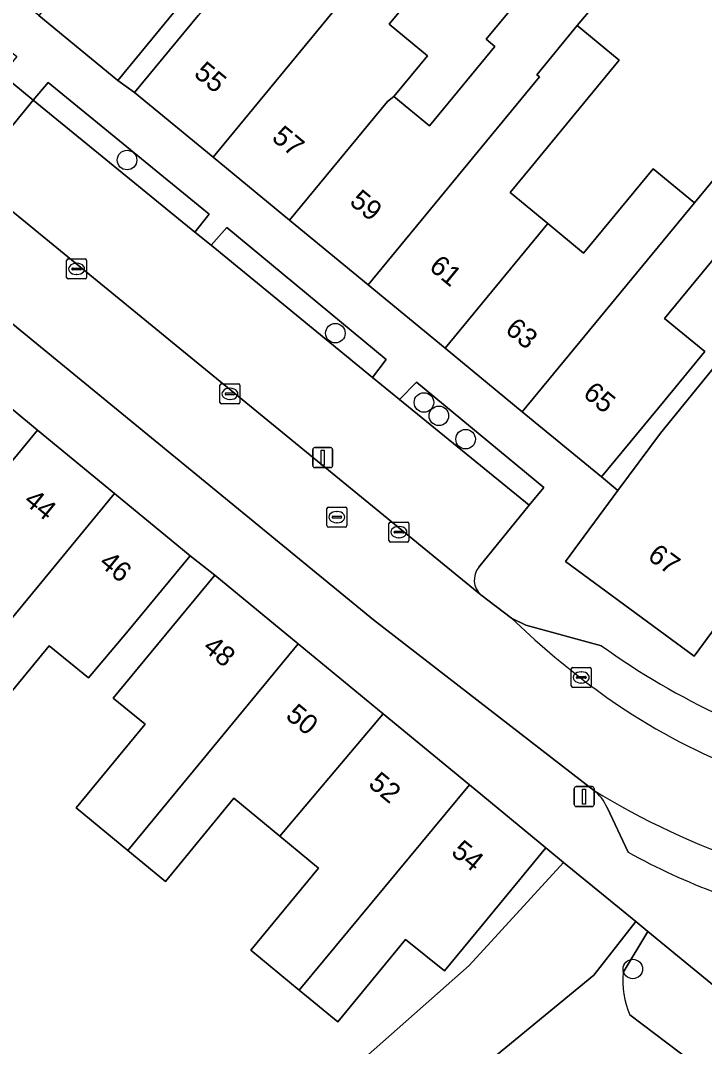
# Model space of a CAD drawing. Extents: x 160157 to 160921, y 381516 to 382045.
# Drawn here: x 160451.2 to 160485.5, y 381805.6 to 381857 of the extents above; entities that cross this region are included whole.
import ezdxf

# ---------------------------------------------------------------- set-up
doc = ezdxf.new("R2010")
doc.units = 0
for name, color, linetype in [('IMGEO_Boom', 7, 'Continuous'), ('IMGEO_Erf', 7, 'Continuous'), ('IMGEO_Groenvoorziening', 7, 'Continuous'), ('IMGEO_Haag', 7, 'Continuous'), ('IMGEO_Kolk', 7, 'Continuous'), ('IMGEO_Lichtmast', 7, 'Continuous'), ('IMGEO_Pand', 7, 'Continuous'), ('IMGEO_Pand_nummerreeks', 7, 'Continuous'), ('IMGEO_Parkeervlak_open', 7, 'Continuous'), ('IMGEO_Rijbaan_lokaal_open', 7, 'Continuous'), ('IMGEO_Rioolput', 7, 'Continuous'), ('IMGEO_Voetpad_open', 7, 'Continuous')]:
    doc.layers.add(name, color=color, linetype=linetype)

msp = doc.modelspace()

# ---------------------------------------------------------------- linework, layer by layer
at = {"layer": 'IMGEO_Boom'}
for centre in [(160456.558, 381849.982), (160466.984, 381841.312), (160471.416, 381837.846), (160472.165, 381837.178), (160473.501, 381836.005), (160481.873, 381809.475)]:
    msp.add_circle(centre, 0.489, dxfattribs=at)
at = {"layer": 'IMGEO_Erf'}
for points in [[(160471.394, 381858.876), (160469.674, 381856.788), (160471.592, 381855.209), (160469.913, 381853.17), (160471.694, 381851.703), (160474.964, 381855.673), (160474.528, 381856.033), (160477.246, 381859.334)], [(160459.274, 381857.827), (160456.095, 381853.967), (160456.94, 381853.363), (160460.119, 381857.223)], [(160479.63, 381857.37), (160479.092, 381856.716), (160481.189, 381854.989), (160479.162, 381852.527), (160476.764, 381849.616), (160475.727, 381848.357), (160477.617, 381846.8), (160479.405, 381845.327), (160482.885, 381849.552), (160484.957, 381847.845), (160488.178, 381851.756)], [(160486.907, 381846.238), (160483.459, 381842.052), (160485.473, 381840.393), (160483.484, 381837.978), (160480.304, 381834.119), (160481.128, 381833.441), (160483.249, 381836.314), (160489.523, 381844.017)], [(160463.455, 381800.599), (160473.68, 381809.649), (160478.409, 381814.815), (160477.522, 381815.543), (160474.343, 381811.684), (160472.453, 381809.383), (160470.492, 381810.944), (160467.104, 381806.83), (160465.181, 381808.414), (160462.754, 381810.413), (160466.144, 381814.529), (160464.2, 381816.13), (160461.903, 381818.022), (160458.478, 381813.864), (160456.602, 381815.409), (160454.011, 381817.543), (160457.458, 381821.727), (160455.872, 381823.033), (160457.769, 381825.336), (160460.948, 381829.195), (160459.714, 381830.173), (160456.536, 381826.314), (160454.63, 381824.057), (160452.667, 381825.655), (160449.283, 381821.546)]]:
    msp.add_lwpolyline(points, dxfattribs=at)
at = {"layer": 'IMGEO_Groenvoorziening'}
for points in [[(160452.613, 381853.874), (160451.861, 381852.989), (160459.954, 381846.377), (160460.677, 381847.27)], [(160461.55, 381846.608), (160460.774, 381845.714), (160468.837, 381839.099), (160469.523, 381839.994)], [(160471.046, 381838.864), (160470.196, 381837.991), (160476.678, 381832.706), (160477.421, 381833.581)], [(160458.371, 381791.432), (160479.918, 381809.167), (160482.021, 381811.85), (160478.409, 381814.815), (160473.68, 381809.649), (160463.455, 381800.599), (160460.339, 381798.072), (160458.209, 381794.524)]]:
    msp.add_lwpolyline(points, close=True, dxfattribs=at)
for points in [[(160481.387, 381809.302), (160482.629, 381811.351), (160482.021, 381811.85), (160479.918, 381809.167), (160458.371, 381791.432), (160458.948, 381780.395), (160474.146, 381779.946), (160474.316, 381782.426), (160495.817, 381780.983), (160495.853, 381781.955), (160492.048, 381782.329), (160492.577, 381797.21), (160490.36, 381800.636), (160481.716, 381807.178)], [(160481.716, 381807.178), (160490.36, 381800.636), (160492.577, 381797.21), (160492.048, 381782.329), (160495.853, 381781.955), (160496.537, 381799.933), (160482.629, 381811.351), (160481.387, 381809.302)]]:
    msp.add_lwpolyline(points, dxfattribs=at)
msp.add_arc((160485.875, 381808.91), 4.505, 175.0051, 202.6048, dxfattribs=at)
msp.add_arc((160485.875, 381808.91), 4.505, 175.0051, 202.6048, dxfattribs=at)
at = {"layer": 'IMGEO_Haag'}
for points in [[(160451.861, 381852.989), (160459.954, 381846.377), (160460.677, 381847.27), (160452.613, 381853.874)], [(160460.774, 381845.714), (160468.837, 381839.099), (160469.523, 381839.994), (160461.55, 381846.608)], [(160476.678, 381832.706), (160477.421, 381833.581), (160471.046, 381838.864), (160470.196, 381837.991)]]:
    msp.add_lwpolyline(points, close=True, dxfattribs=at)
at = {"layer": 'IMGEO_Kolk'}
for p, q in [((160453.535, 381844.107), (160453.535, 381844.959)), ((160453.61, 381845.033), (160454.462, 381845.033)), ((160453.794, 381844.527), (160453.794, 381844.539)), ((160453.837, 381844.576), (160454.235, 381844.576)), ((160454.023, 381844.813), (160454.048, 381844.813)), ((160454.278, 381844.539), (160454.278, 381844.527)), ((160454.536, 381844.959), (160454.536, 381844.107)), ((160454.462, 381844.033), (160453.61, 381844.033)), ((160454.232, 381844.49), (160453.834, 381844.49)), ((160454.046, 381844.253), (160454.021, 381844.253)), ((160461.209, 381837.851), (160461.209, 381838.703)), ((160461.284, 381838.777), (160462.136, 381838.777)), ((160461.697, 381838.557), (160461.722, 381838.557)), ((160462.21, 381838.703), (160462.21, 381837.851)), ((160461.468, 381838.271), (160461.468, 381838.283)), ((160461.906, 381838.234), (160461.508, 381838.234)), ((160461.511, 381838.32), (160461.909, 381838.32)), ((160461.72, 381837.997), (160461.695, 381837.997)), ((160461.952, 381838.283), (160461.952, 381838.271)), ((160462.136, 381837.777), (160461.284, 381837.777)), ((160469.666, 381830.928), (160469.666, 381831.78)), ((160469.741, 381831.854), (160470.593, 381831.854)), ((160470.667, 381831.78), (160470.667, 381830.928)), ((160469.925, 381831.348), (160469.925, 381831.36)), ((160470.363, 381831.311), (160469.965, 381831.311)), ((160469.968, 381831.397), (160470.366, 381831.397)), ((160470.154, 381831.634), (160470.179, 381831.634)), ((160470.409, 381831.36), (160470.409, 381831.348)), ((160470.593, 381830.854), (160469.741, 381830.854)), ((160470.177, 381831.074), (160470.152, 381831.074)), ((160478.791, 381823.65), (160478.791, 381824.502)), ((160478.866, 381824.576), (160479.718, 381824.576)), ((160479.792, 381824.502), (160479.792, 381823.65)), ((160479.05, 381824.07), (160479.05, 381824.082)), ((160479.488, 381824.033), (160479.09, 381824.033)), ((160479.093, 381824.119), (160479.491, 381824.119)), ((160479.279, 381824.356), (160479.304, 381824.356)), ((160479.534, 381824.082), (160479.534, 381824.07)), ((160479.718, 381823.576), (160478.866, 381823.576)), ((160479.302, 381823.796), (160479.277, 381823.796))]:
    msp.add_line(p, q, dxfattribs=at)
for points in [[(160453.535, 381844.107), (160453.535, 381844.959)], [(160453.61, 381845.033), (160454.462, 381845.033)], [(160454.536, 381844.959), (160454.536, 381844.107)], [(160454.462, 381844.033), (160453.61, 381844.033)], [(160461.209, 381837.851), (160461.209, 381838.703)], [(160461.284, 381838.777), (160462.136, 381838.777)], [(160462.21, 381838.703), (160462.21, 381837.851)], [(160462.136, 381837.777), (160461.284, 381837.777)], [(160469.666, 381830.928), (160469.666, 381831.78)], [(160469.741, 381831.854), (160470.593, 381831.854)], [(160470.667, 381831.78), (160470.667, 381830.928)], [(160470.593, 381830.854), (160469.741, 381830.854)], [(160478.791, 381823.65), (160478.791, 381824.502)], [(160478.866, 381824.576), (160479.718, 381824.576)], [(160479.792, 381824.502), (160479.792, 381823.65)], [(160479.718, 381823.576), (160478.866, 381823.576)]]:
    msp.add_lwpolyline(points, dxfattribs=at)
for centre, radius, start, end in [((160453.612, 381844.957), 0.0765, 91.552, 178.448), ((160453.612, 381844.957), 0.0765, 91.552, 178.448), ((160453.834, 381844.536), 0.0403, 85.8775, 175.7526), ((160454.239, 381844.538), 0.0386, 1.7309, 96.639), ((160454.46, 381844.957), 0.0765, 1.552, 88.448), ((160454.46, 381844.957), 0.0765, 1.552, 88.448), ((160453.612, 381844.109), 0.0765, 181.552, 268.448), ((160453.612, 381844.109), 0.0765, 181.552, 268.448), ((160453.831, 381844.526), 0.0366, 178.938, 274.7102), ((160454.235, 381844.533), 0.043, 264.8664, 352.4533), ((160454.46, 381844.109), 0.0765, 271.552, 358.448), ((160454.46, 381844.109), 0.0765, 271.552, 358.448), ((160461.286, 381838.701), 0.0765, 91.552, 178.448), ((160461.286, 381838.701), 0.0765, 91.552, 178.448), ((160462.134, 381838.701), 0.0765, 1.552, 88.448), ((160462.134, 381838.701), 0.0765, 1.552, 88.448), ((160461.508, 381838.28), 0.0403, 85.8775, 175.7526), ((160461.505, 381838.27), 0.0366, 178.938, 274.7102), ((160461.909, 381838.277), 0.043, 264.8664, 352.4533), ((160461.913, 381838.282), 0.0386, 1.7309, 96.639), ((160461.286, 381837.853), 0.0765, 181.552, 268.448), ((160461.286, 381837.853), 0.0765, 181.552, 268.448), ((160462.134, 381837.853), 0.0765, 271.552, 358.448), ((160462.134, 381837.853), 0.0765, 271.552, 358.448), ((160469.743, 381831.778), 0.0765, 91.552, 178.448), ((160469.743, 381831.778), 0.0765, 91.552, 178.448), ((160470.591, 381831.778), 0.0765, 1.552, 88.448), ((160470.591, 381831.778), 0.0765, 1.552, 88.448), ((160469.965, 381831.357), 0.0403, 85.8775, 175.7526), ((160469.962, 381831.347), 0.0366, 178.938, 274.7102), ((160470.366, 381831.354), 0.043, 264.8664, 352.4533), ((160470.37, 381831.359), 0.0386, 1.7309, 96.639), ((160469.743, 381830.93), 0.0765, 181.552, 268.448), ((160469.743, 381830.93), 0.0765, 181.552, 268.448), ((160470.591, 381830.93), 0.0765, 271.552, 358.448), ((160470.591, 381830.93), 0.0765, 271.552, 358.448), ((160478.868, 381824.5), 0.0765, 91.552, 178.448), ((160478.868, 381824.5), 0.0765, 91.552, 178.448), ((160479.716, 381824.5), 0.0765, 1.552, 88.448), ((160479.716, 381824.5), 0.0765, 1.552, 88.448), ((160479.09, 381824.079), 0.0403, 85.8775, 175.7526), ((160479.087, 381824.069), 0.0366, 178.938, 274.7102), ((160479.491, 381824.076), 0.043, 264.8664, 352.4533), ((160479.495, 381824.081), 0.0386, 1.7309, 96.639), ((160478.868, 381823.652), 0.0765, 181.552, 268.448), ((160478.868, 381823.652), 0.0765, 181.552, 268.448), ((160479.716, 381823.652), 0.0765, 271.552, 358.448), ((160479.716, 381823.652), 0.0765, 271.552, 358.448)]:
    msp.add_arc(centre, radius, start, end, dxfattribs=at)
for centre, major_axis, ratio, start_param, end_param in [((160454.022, 381844.533), (-0.387, 0.002), 0.722429, 4.712389, 7.853982), ((160454.047, 381844.533), (-0.39, 0.002), 0.717154, 1.570796, 4.712389), ((160461.696, 381838.277), (-0.387, 0.002), 0.722429, 4.712389, 7.853982), ((160461.721, 381838.277), (-0.39, 0.002), 0.717154, 1.570796, 4.712389), ((160470.153, 381831.354), (-0.387, 0.002), 0.722429, 4.712389, 7.853982), ((160470.178, 381831.354), (-0.39, 0.002), 0.717154, 1.570796, 4.712389), ((160479.278, 381824.076), (-0.387, 0.002), 0.722429, 4.712389, 7.853982), ((160479.303, 381824.076), (-0.39, 0.002), 0.717154, 1.570796, 4.712389)]:
    msp.add_ellipse(centre, major_axis=major_axis, ratio=ratio, start_param=start_param, end_param=end_param, dxfattribs=at)
at = {"layer": 'IMGEO_Lichtmast'}
for p, q in [((160465.854, 381834.684), (160465.854, 381835.484)), ((160465.854, 381835.484), (160465.854, 381834.684)), ((160465.954, 381835.584), (160466.744, 381835.584)), ((160466.744, 381835.584), (160465.954, 381835.584)), ((160466.844, 381835.484), (160466.844, 381834.684)), ((160466.844, 381834.684), (160466.844, 381835.484)), ((160466.744, 381834.584), (160465.954, 381834.584)), ((160465.954, 381834.584), (160466.744, 381834.584)), ((160478.94, 381817.712), (160478.94, 381818.512)), ((160478.94, 381818.512), (160478.94, 381817.712)), ((160479.04, 381818.612), (160479.83, 381818.612)), ((160479.83, 381818.612), (160479.04, 381818.612)), ((160479.93, 381818.512), (160479.93, 381817.712)), ((160479.93, 381817.712), (160479.93, 381818.512)), ((160479.83, 381817.612), (160479.04, 381817.612)), ((160479.04, 381817.612), (160479.83, 381817.612))]:
    msp.add_line(p, q, dxfattribs=at)
for points in [[(160466.274, 381835.459), (160466.424, 381835.459), (160466.424, 381834.709), (160466.274, 381834.709), (160466.274, 381835.459)], [(160479.36, 381818.487), (160479.51, 381818.487), (160479.51, 381817.737), (160479.36, 381817.737), (160479.36, 381818.487)]]:
    msp.add_lwpolyline(points, dxfattribs=at)
for centre, start, end in [((160465.954, 381835.484), 90, 180), ((160465.954, 381835.484), 90, 180), ((160466.744, 381835.484), 0, 90), ((160466.744, 381835.484), 360, 90), ((160465.954, 381834.684), 180, 270), ((160465.954, 381834.684), 180, 270), ((160466.744, 381834.684), 270, 0), ((160466.744, 381834.684), 270, 0), ((160479.04, 381818.512), 90, 180), ((160479.04, 381818.512), 90, 180), ((160479.83, 381818.512), 0, 90), ((160479.83, 381818.512), 360, 90), ((160479.04, 381817.712), 180, 270), ((160479.04, 381817.712), 180, 270), ((160479.83, 381817.712), 270, 0), ((160479.83, 381817.712), 270, 0)]:
    msp.add_arc(centre, 0.1, start, end, dxfattribs=at)
at = {"layer": 'IMGEO_Pand'}
for points in [[(160460.843, 381867.566), (160452.138, 381857.227), (160456.095, 381853.967), (160459.274, 381857.827), (160461.232, 381860.205), (160459.299, 381861.797), (160462.754, 381865.991)], [(160469.412, 381860.508), (160467.333, 381862.221), (160465.488, 381863.741), (160462.036, 381859.55), (160460.119, 381857.223), (160456.94, 381853.363), (160460.864, 381850.131)], [(160469.412, 381860.508), (160460.864, 381850.131), (160464.696, 381846.974), (160469.59, 381852.916), (160469.913, 381853.17), (160471.592, 381855.209), (160469.674, 381856.788), (160471.394, 381858.876)], [(160479.092, 381856.716), (160479.63, 381857.37), (160477.246, 381859.334), (160474.528, 381856.033), (160474.964, 381855.673), (160471.694, 381851.703), (160469.913, 381853.17), (160469.59, 381852.916), (160464.696, 381846.974), (160468.622, 381843.741), (160477.193, 381854.149), (160477.065, 381854.255)], [(160475.727, 381848.357), (160476.764, 381849.616), (160479.162, 381852.527), (160481.189, 381854.989), (160479.092, 381856.716), (160477.065, 381854.255), (160477.193, 381854.149), (160468.622, 381843.741), (160472.481, 381840.563), (160477.617, 381846.8)], [(160483.459, 381842.052), (160486.907, 381846.238), (160490.129, 381850.149), (160488.178, 381851.756), (160484.957, 381847.845), (160476.341, 381837.384), (160480.304, 381834.119), (160483.484, 381837.978), (160485.473, 381840.393)], [(160477.617, 381846.8), (160472.481, 381840.563), (160476.341, 381837.384), (160484.957, 381847.845), (160482.885, 381849.552), (160479.405, 381845.327)], [(160489.609, 381831.618), (160489.422, 381831.756), (160493.577, 381836.913), (160492.694, 381837.625), (160493.273, 381838.344), (160492.975, 381838.584), (160494.435, 381840.297), (160489.523, 381844.017), (160483.249, 381836.314), (160481.128, 381833.441), (160478.504, 381829.886), (160484.936, 381825.138), (160487.416, 381828.497), (160487.323, 381828.564)], [(160452.077, 381836.463), (160448.406, 381839.488), (160443.287, 381833.299), (160443.023, 381833.517), (160439.599, 381829.365), (160439.859, 381829.155), (160441.282, 381828.006), (160439.398, 381825.673), (160441.698, 381823.816), (160443.582, 381826.149)], [(160447.474, 381823.007), (160450.737, 381826.969), (160455.926, 381833.293), (160452.077, 381836.463), (160443.582, 381826.149)], [(160452.667, 381825.655), (160454.63, 381824.057), (160456.536, 381826.314), (160459.714, 381830.173), (160455.926, 381833.293), (160450.737, 381826.969), (160447.474, 381823.007), (160449.283, 381821.546)], [(160456.602, 381815.409), (160465.126, 381825.753), (160460.948, 381829.195), (160457.769, 381825.336), (160455.872, 381823.033), (160457.458, 381821.727), (160454.011, 381817.543)], [(160469.377, 381822.252), (160465.126, 381825.753), (160456.602, 381815.409), (160458.478, 381813.864), (160461.903, 381818.022), (160464.2, 381816.13)], [(160473.701, 381818.691), (160469.377, 381822.252), (160464.2, 381816.13), (160466.144, 381814.529), (160462.754, 381810.413), (160465.181, 381808.414)], [(160473.701, 381818.691), (160465.181, 381808.414), (160467.104, 381806.83), (160470.492, 381810.944), (160472.453, 381809.383), (160474.343, 381811.684), (160477.522, 381815.543)]]:
    msp.add_lwpolyline(points, close=True, dxfattribs=at)
at = {"layer": 'IMGEO_Parkeervlak_open'}
for points in [[(160460.774, 381845.714), (160459.954, 381846.377), (160451.861, 381852.989), (160448.706, 381849.132), (160474.266, 381828.22)], [(160474.16, 381829.592), (160476.678, 381832.706), (160470.196, 381837.991), (160468.837, 381839.099), (160460.774, 381845.714)], [(160480.308, 381825.664), (160476.51, 381826.689), (160475.803, 381827.039), (160476.974, 381825.958)], [(160480.58, 381817.558), (160481.638, 381815.33)]]:
    msp.add_lwpolyline(points, dxfattribs=at)
for centre, radius, start, end in [((160474.931, 381828.961), 0.996, 140.7314, 228.1043), ((160506.37, 381858.968), 44.202, 228.3147, 235.141), ((160501.525, 381854.933), 36.15, 234.0616, 256.3354), ((160500.209, 381851.371), 34.454, 236.3269, 248.3483), ((160499.758, 381850.577), 37.779, 238.2924, 251.4783), ((160478.583, 381816.719), 2.166, 22.7987, 52.4896), ((160497.263, 381843.305), 32.043, 240.8151, 258.495)]:
    msp.add_arc(centre, radius, start, end, dxfattribs=at)
at = {"layer": 'IMGEO_Rijbaan_lokaal_open'}
for points in [[(160371.41, 381914.519), (160389.742, 381899.391), (160409.362, 381883.2), (160421.079, 381873.531), (160420.73, 381873.107), (160425.014, 381863.084), (160439.434, 381851.118), (160468.894, 381826.952), (160479.902, 381818.437)], [(160476.974, 381825.958), (160475.803, 381827.039), (160474.266, 381828.22), (160448.706, 381849.132), (160447.149, 381850.406), (160434.38, 381860.853), (160429.948, 381864.485)]]:
    msp.add_lwpolyline(points, dxfattribs=at)
for centre, radius, start, end in [((160506.37, 381858.968), 44.202, 228.3147, 235.141), ((160500.209, 381851.371), 34.454, 236.3269, 248.3483), ((160499.758, 381850.577), 37.779, 238.2924, 251.4783)]:
    msp.add_arc(centre, radius, start, end, dxfattribs=at)
at = {"layer": 'IMGEO_Rioolput'}
for p, q in [((160466.56, 381831.676), (160466.56, 381832.528)), ((160466.635, 381832.602), (160467.487, 381832.602)), ((160467.048, 381832.382), (160467.073, 381832.382)), ((160467.561, 381832.528), (160467.561, 381831.676)), ((160466.819, 381832.096), (160466.819, 381832.108)), ((160467.257, 381832.059), (160466.859, 381832.059)), ((160466.862, 381832.145), (160467.26, 381832.145)), ((160467.071, 381831.822), (160467.046, 381831.822)), ((160467.303, 381832.108), (160467.303, 381832.096)), ((160467.487, 381831.602), (160466.635, 381831.602))]:
    msp.add_line(p, q, dxfattribs=at)
for points in [[(160466.56, 381831.676), (160466.56, 381832.528)], [(160466.635, 381832.602), (160467.487, 381832.602)], [(160467.561, 381832.528), (160467.561, 381831.676)], [(160467.487, 381831.602), (160466.635, 381831.602)]]:
    msp.add_lwpolyline(points, dxfattribs=at)
for centre, radius, start, end in [((160466.637, 381832.526), 0.0765, 91.552, 178.448), ((160466.637, 381832.526), 0.0765, 91.552, 178.448), ((160467.485, 381832.526), 0.0765, 1.552, 88.448), ((160467.485, 381832.526), 0.0765, 1.552, 88.448), ((160466.859, 381832.105), 0.0403, 85.8775, 175.7526), ((160466.856, 381832.095), 0.0366, 178.938, 274.7102), ((160467.26, 381832.102), 0.043, 264.8664, 352.4533), ((160467.264, 381832.107), 0.0386, 1.7309, 96.639), ((160466.637, 381831.678), 0.0765, 181.552, 268.448), ((160466.637, 381831.678), 0.0765, 181.552, 268.448), ((160467.485, 381831.678), 0.0765, 271.552, 358.448), ((160467.485, 381831.678), 0.0765, 271.552, 358.448)]:
    msp.add_arc(centre, radius, start, end, dxfattribs=at)
for centre, major_axis, ratio, start_param, end_param in [((160467.047, 381832.102), (-0.387, 0.002), 0.722429, 4.712389, 7.853982), ((160467.072, 381832.102), (-0.39, 0.002), 0.717154, 1.570796, 4.712389)]:
    msp.add_ellipse(centre, major_axis=major_axis, ratio=ratio, start_param=start_param, end_param=end_param, dxfattribs=at)
at = {"layer": 'IMGEO_Voetpad_open'}
for points in [[(160487.416, 381828.497), (160484.936, 381825.138), (160478.504, 381829.886), (160481.128, 381833.441), (160480.304, 381834.119), (160476.341, 381837.384), (160472.481, 381840.563), (160468.622, 381843.741), (160464.696, 381846.974), (160460.864, 381850.131), (160456.94, 381853.363), (160456.095, 381853.967), (160452.138, 381857.227), (160448.278, 381860.406), (160444.419, 381863.584), (160440.462, 381866.844), (160439.735, 381867.434), (160435.49, 381870.93), (160431.336, 381874.352), (160427.065, 381877.87), (160422.742, 381881.431), (160417.865, 381885.448), (160409.913, 381891.762)], [(160479.902, 381818.437), (160468.894, 381826.952), (160439.434, 381851.118), (160425.014, 381863.084), (160420.73, 381873.107)], [(160430.491, 381866.146), (160432.586, 381868.697), (160433.34, 381869.591), (160442.468, 381862.168), (160441.767, 381861.247), (160442.582, 381860.578), (160443.307, 381861.473), (160451.047, 381855.17), (160450.302, 381854.26), (160451.861, 381852.989), (160452.613, 381853.874), (160460.677, 381847.27), (160459.954, 381846.377), (160460.774, 381845.714), (160461.55, 381846.608), (160469.523, 381839.994), (160468.837, 381839.099), (160470.196, 381837.991), (160471.046, 381838.864), (160477.421, 381833.581), (160476.678, 381832.706), (160474.16, 381829.592)], [(160448.406, 381839.488), (160452.077, 381836.463), (160455.926, 381833.293), (160459.714, 381830.173), (160460.948, 381829.195), (160465.126, 381825.753), (160469.377, 381822.252), (160473.701, 381818.691), (160477.522, 381815.543), (160478.409, 381814.815), (160482.021, 381811.85), (160482.629, 381811.351), (160496.537, 381799.933), (160495.66, 381810.687)], [(160474.266, 381828.22), (160475.803, 381827.039), (160476.51, 381826.689), (160480.308, 381825.664)], [(160481.638, 381815.33), (160480.58, 381817.558)]]:
    msp.add_lwpolyline(points, dxfattribs=at)
msp.add_lwpolyline([(160451.861, 381852.989), (160450.302, 381854.26), (160447.149, 381850.406), (160448.706, 381849.132)], close=True, dxfattribs=at)
for centre, radius, start, end in [((160474.931, 381828.961), 0.996, 140.7314, 228.1043), ((160501.525, 381854.933), 36.15, 234.0616, 256.3354), ((160478.583, 381816.719), 2.166, 22.7987, 52.4896), ((160497.263, 381843.305), 32.043, 240.8151, 258.495)]:
    msp.add_arc(centre, radius, start, end, dxfattribs=at)

# ---------------------------------------------------------------- texts
at = {"layer": 'IMGEO_Pand_nummerreeks'}
for s, rotation, p in [('55', 320.5232, (160459.852, 381854.23)), ('57', 320.5231, (160463.746, 381851.022)), ('59', 320.5232, (160467.64, 381847.815)), ('61', 320.5232, (160471.621, 381844.537)), ('63', 320.5231, (160475.428, 381841.4)), ('65', 320.5232, (160479.322, 381838.193)), ('44', 320.5221, (160451.337, 381832.824)), ('67', 323.5656, (160482.552, 381830.031)), ('46', 320.5232, (160455.107, 381829.719)), ('48', 320.5217, (160460.299, 381825.481)), ('50', 320.5217, (160464.442, 381822.068)), ('52', 320.5217, (160468.581, 381818.658)), ('54', 320.5217, (160472.727, 381815.243))]:
    msp.add_text(s, height=1, rotation=rotation, dxfattribs=at).set_placement(p)

doc.saveas('drawing.dxf')
